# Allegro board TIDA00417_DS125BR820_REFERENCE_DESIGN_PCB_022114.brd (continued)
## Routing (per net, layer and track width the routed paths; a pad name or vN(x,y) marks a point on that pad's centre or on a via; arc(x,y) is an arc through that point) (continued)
BOT_ING_LN3_HOST_N: length 70.5
  TOP w0.178: C35.1 135.91,67.56 135.91,71.36 arc(136.14,71.91) 136.69,72.14 arc(137.36,72.41) 137.63,73.08 137.63,73.79 arc(116.37,77.13) U3.12
BOT_ING_LN3_HOST_P: length 46.1
  TOP w0.178: C34.1 135.35,67.56 135.35,71.36 arc(135.13,71.91) 134.58,72.14 arc(133.91,72.41) 133.63,73.08 133.63,73.9 arc(120.37,77.07) U3.11
BOT_ING_LN3_N: length 109.2
  TOP w0.178: U1.13 140.56,45.87 140.56,43.76 arc(140.68,43.16) 141.02,42.65 141.98,41.69 arc(142.53,40.86) 142.73,39.89 142.73,38.23 arc(142.75,38.12) 142.81,38.02 v2(142.89,37.95)
  SIG-3 w0.203: U5.L21 53.74,44.2 arc(53.97,44.15) 54.17,44.02 54.19,44.01 54.19,44 55.56,42.63 arc(57.69,41.21) 60.21,40.71 79.41,40.71 arc(81.66,40.26) 83.58,38.98 88.62,33.93 90.87,31.68 arc(93.36,30.02) 96.3,29.44 136.73,29.44 arc(141.02,31.22) 142.8,35.51 142.8,37.73 arc(142.82,37.85) v2(142.89,37.95)
BOT_ING_LN3_P: length 109.2
  TOP w0.178: U1.12 140,45.87 140,43.76 arc(140.16,42.95) 140.62,42.26 141.59,41.29 arc(142.02,40.65) 142.17,39.89 142.17,38.23 arc(142.17,38.22) 142.17,38.21 arc(142.15,38.12) 142.1,38.05 v2(142,37.95)
  SIG-3 w0.203: U5.L22 54.79,44.9 arc(54.72,44.79) 54.69,44.65 54.69,44.59 arc(54.71,44.51) 54.75,44.45 56.06,43.14 arc(57.96,41.87) 60.21,41.42 79.41,41.42 arc(81.94,40.92) 84.08,39.48 84.44,39.13 arc(84.57,39.04) 84.72,39.01 85.23,39.01 arc(85.41,38.97) 85.57,38.87 arc(85.67,38.72) 85.71,38.53 85.71,38.19 85.71,38.19 85.71,38.02 arc(85.74,37.87) 85.82,37.74 88.59,34.98 arc(88.8,34.84) 89.05,34.79 89.06,34.79 arc(89.29,34.74) 89.5,34.6 arc(89.63,34.4) 89.68,34.16 89.68,34.11 arc(89.72,33.9) 89.84,33.73 89.87,33.7 arc(90.01,33.6) 90.18,33.57 90.37,33.57 arc(90.57,33.53) 90.74,33.41 arc(90.86,33.24) 90.9,33.03 90.9,32.81 arc(90.93,32.68) 91,32.56 91.38,32.19 arc(93.63,30.68) 96.3,30.15 96.52,30.15 arc(96.73,30.19) 96.9,30.31 96.95,30.35 arc(97.14,30.49) 97.38,30.53 arc(97.61,30.49) 97.81,30.35 97.82,30.34 arc(98.03,30.2) 98.28,30.15 98.7,30.15 arc(98.95,30.2) 99.16,30.34 arc(99.38,30.48) 99.63,30.53 99.8,30.53 arc(99.97,30.5) 100.11,30.41 100.17,30.34 arc(100.38,30.2) 100.63,30.15 131.87,30.15 arc(132.29,30.23) 132.65,30.47 arc(132.83,30.59) 133.04,30.63 arc(133.36,30.57) 133.63,30.39 arc(133.9,30.21) 134.21,30.15 arc(134.52,30.21) 134.78,30.39 arc(135.06,30.57) 135.38,30.63 135.58,30.63 arc(135.76,30.6) 135.91,30.49 136.02,30.39 arc(136.29,30.21) 136.6,30.15 136.73,30.15 arc(140.52,31.72) 142.09,35.51 142.09,37.73 arc(142.07,37.85) v2(142,37.95)
BOT_ING_LN4_HOST_N: length 22.4
  TOP w0.127: 129.63,76.01 U3.10
  TOP w0.178: C25.1 127.91,67.56 127.91,71.36 arc(128.14,71.91) 128.69,72.14 arc(129.36,72.41) 129.63,73.08 129.63,73.87 arc(124.37,77.09) U3.10
BOT_ING_LN4_HOST_P: length 9.5
  TOP w0.178: C24.1 127.35,67.56 127.35,71.36 arc(127.13,71.91) 126.58,72.14 arc(125.91,72.41) 125.63,73.08 125.63,73.98 arc(125.63,75) U3.9
BOT_ING_LN4_N: length 100.9
  TOP w0.178: U1.2 135.06,45.87 135.06,45.4 arc(134.46,43.96) 133.02,43.37 132,43.37 arc(131.8,43.32) v1(131.64,43.2)
  BOTTOM w0.178: U5.L24 53.93,46.6 arc(53.98,46.6) 54.03,46.59 arc(54.15,46.54) 54.25,46.47 54.46,46.26 arc(54.99,45.9) 55.61,45.77 arc(55.62,45.77) 55.62,45.77 arc(55.99,45.57) 56.13,45.18 56.13,43.97 arc(56.24,43.43) 56.54,42.97 56.81,42.7 arc(57.47,42.26) 58.25,42.11 65.2,42.11 arc(66.54,42.37) 67.67,43.13 arc(68.26,43.52) 68.96,43.66 81.06,43.66 arc(82.81,43.31) 84.3,42.32 86.62,40 arc(88.1,37.78) 88.62,35.16 88.62,34.37 arc(88.81,33.4) 89.36,32.59 89.93,32.01 90.83,31.11 91.96,29.98 arc(94.41,28.34) 97.3,27.77 110.19,27.77 arc(113.92,28.51) 117.08,30.62 126.96,40.51 129.14,42.68 arc(129.89,43.19) 130.79,43.37 131.27,43.37 arc(131.47,43.32) v1(131.64,43.2)
BOT_ING_LN4_P: length 100
  TOP w0.178: U1.1 134.53,45.9 134.5,45.87 134.5,45.4 arc(134.07,44.36) 133.02,43.92 132,43.92 arc(131.99,43.92) 131.97,43.92 arc(131.82,43.95) 131.69,44.04 v1(131.64,44.09)
  BOTTOM w0.178: U5.L25 54.65,47.15 arc(54.59,47.01) 54.65,46.86 54.86,46.65 arc(55.21,46.41) 55.62,46.33 arc(55.64,46.33) 55.65,46.33 arc(55.67,46.32) 55.7,46.32 arc(56.41,45.94) 56.69,45.18 56.69,43.97 arc(56.76,43.64) 56.94,43.37 57.21,43.1 arc(57.69,42.78) 58.25,42.67 65.2,42.67 arc(66.32,42.89) 67.27,43.53 arc(68.05,44.04) 68.96,44.22 81.06,44.22 arc(83.02,43.83) 84.69,42.72 87.01,40.4 arc(88.62,38) 89.18,35.16 89.18,34.37 arc(89.33,33.62) 89.75,32.98 90.09,32.64 arc(90.25,32.54) 90.42,32.5 90.53,32.5 arc(90.56,32.5) 90.59,32.49 90.68,32.46 arc(90.78,32.4) 90.88,32.32 90.9,32.3 arc(91.04,32.09) 91.09,31.84 arc(91.13,31.66) 91.23,31.51 92.36,30.38 arc(94.63,28.86) 97.3,28.33 105.95,28.33 arc(106.19,28.38) 106.4,28.52 106.44,28.55 arc(106.58,28.65) 106.75,28.68 106.77,28.68 arc(106.92,28.65) 107.04,28.57 107.16,28.46 arc(107.3,28.36) 107.47,28.33 107.53,28.33 arc(107.75,28.37) 107.94,28.5 108.01,28.57 arc(108.1,28.63) 108.19,28.65 108.37,28.65 arc(108.54,28.62) 108.69,28.52 arc(108.9,28.38) 109.14,28.33 110.19,28.33 arc(113.7,29.03) 116.68,31.02 128.74,43.08 arc(129.68,43.7) 130.79,43.92 131.27,43.92 arc(131.47,43.97) v1(131.64,44.09)
BOT_INTL: length 33.8
  TOP w0.203: R81.1 J4.14
  SIG-1 w0.201: J4.14 42.87,29.65 44.76,29.65 45.41,30.29 45.41,34.33 47.38,36.31 50.57,36.31 56.05,41.79 56.05,48.12 54.9,49.27 U5.L28
BOT_LPMODE: length 40.9
  SIG-1 w0.201: J4.18 38.84,28.59 46.95,28.59 47.83,29.47 47.83,34.49 48.64,35.31 50.88,35.31 56.44,40.86 56.44,48.64 56.16,48.91 56.16,50.93 U5.L31
BOT_MODPRSL: length 40.8
  TOP w0.203: R82.1 J4.12
  SIG-1 w0.201: J4.12 44.11,31.05 42.88,32.28 42.88,35.89 44.48,37.5 49.46,37.5 52.18,40.22 52.18,47.69 U5.L27
  BOTTOM w0.203: J4.12 42.12,28.96 35.65,28.96 33.95,30.66 J4.20
BOT_MODSELL: length 30.9
  BOTTOM w0.203: U5.L8 42.9,52.2 40.28,49.59 40.28,32.25 39.03,31 J4.16
QSFP_RESETL: length 29.2
  TOP w0.203: U5.L9 51.75,51.4 52.52,52.17 53.82,52.17 54.59,51.4 U5.U9
  SIG-1 w0.201: SW20.1 43.95,69.51 47.12,66.34 47.12,53.77 U5.L9
QSFP_SCL: length 49.1
  TOP w0.203: SW19.3 v1(32.63,68.34) ; U5.L11 51.91,49.8 52.18,50.06 53.38,50.06 54.28,49.17 55.61,49.17 56.24,49.8 U5.U11
  SIG-1 w0.201: v1(32.63,68.34) 33.24,67.73 37.6,67.73 40.79,70.92 45.06,70.92 52.16,63.83 52.16,51.06 U5.L11
QSFP_SDA: length 51.1
  TOP w0.203: SW19.4 v1(35.17,68.39)
  SIG-1 w0.201: v1(35.17,68.39) 36.84,68.39 40.47,72.02 47.13,72.02 56.22,62.93 56.22,51.97 56.95,51.24 56.95,49.54 U5.U12
  BOTTOM w0.203: U5.U12 54.39,49 53.65,49.74 52.72,49.74 51.98,49 U5.L12
QSFP_VCC_3P3V: length 3.6
  TOP w0.508: R84.2 v1(46.65,25.82) ; R82.2 v1(44.11,25.82) ; R83.2 v1(54.27,25.82) ; R81.2 v1(41.57,25.82)
  vias: v1(24.95,73.7) v1(25.03,71.22) v1(25.98,73.13) v1(26.02,72.37) v1(26,70.77) v1(25.99,70.09)
RT1_DEMA0_SDA: length 120.4
  TOP w0.203: v1(131.28,49.29) 131.28,49.3 131.64,49.66 132.59,49.66 133.19,49.05 U1.49
  TOP w0.508: v1(192.82,2.58) 192.82,2.57 190.55,2.57 SW13.1
  SIG-1 w0.201: v1(192.82,2.58) 201.61,11.37 201.61,23.59 v1(200.04,25.16)
  SIG-3 w0.201: v1(131.28,49.29) 131.64,49.64 132.79,49.64 134.35,48.08 134.35,44.32 135.03,43.64 181.55,43.64 v1(200.04,25.16)
  BOTTOM w0.508: SW11.10 SW11.11 SW11.12 v1(200.04,25.16)
RT1_DEMA1_SCL: length 112.4
  TOP w0.203: U1.50 132.59,48.55 132.44,48.4 v1(131.33,48.4) ; SW13.2 196.25,5.12 199.86,8.73 v1(199.86,16.52)
  SIG-3 w0.201: v1(131.33,48.4) 131.81,47.92 131.81,47.61 132.35,47.08 133.01,47.08 133.97,46.11 133.97,43.81 134.73,43.05 173.34,43.05 v1(199.86,16.52)
  BOTTOM w0.508: SW11.7 SW11.8 SW11.9 200.4,17.54 199.86,17 v1(199.86,16.52)
RT1_DEMB0_AD1: length 98.6
  TOP w0.203: v1(130.35,48.26) 130.35,47.4 130.89,46.86 132.03,46.86 132.05,46.89 133.22,46.89 133.39,47.05 U1.53
  TOP w0.508: v1(200.04,53.1) SW12.10 SW12.11 SW12.12
  SIG-1 w0.201: v1(130.35,48.26) 130.04,48.58 130.04,57.95 132.88,60.79 196.02,60.79 200.67,56.15 200.67,53.73 v1(200.04,53.1)
RT1_DEMB1_AD0: length 96.8
  TOP w0.203: v1(130.11,46.7) 130.96,45.85 132.79,45.85 133.49,46.55 133.88,46.55 U1.54
  TOP w0.508: SW12.9 SW12.8 SW12.7 v1(200.04,60.72)
  SIG-1 w0.201: v1(200.04,60.72) 198.5,62.26 132.84,62.26 129.04,58.46 129.04,47.76 v1(130.11,46.7)
RT1_ENSMB: length 83.1
  TOP w0.203: U1.48 133.43,49.55 132.77,50.22 v1(131.7,50.22)
  SIG-1 w0.201: v1(199.66,55.64) 198.23,57.06 142.83,57.06 140.67,54.9 133.87,54.9 131.19,52.22 131.19,50.72 v1(131.7,50.22)
  BOTTOM w0.508: SW18.12 SW18.11 SW18.10 v1(199.66,55.64)
RT1_EQA0: length 67.3
  TOP w0.203: U1.20 145.11,47.05 v1(145.43,46.73)
  SIG-1 w0.201: v1(145.43,46.73) 145.43,46.73 145.38,46.78 146.3,45.86 191.66,45.86 v1(199.66,37.86)
  BOTTOM w0.508: v1(199.66,37.86) SW14.10 SW14.11 SW14.12
RT1_EQA1: length 70.1
  TOP w0.203: U1.19 v1(144.49,46.55)
  SIG-1 w0.201: v1(144.49,46.55) 144.49,46.55 147.21,43.83 186.07,43.83 v1(199.66,30.24)
  BOTTOM w0.508: SW14.9 SW14.8 SW14.7 v1(199.66,30.24)
RT1_EQB0_AD3: length 85.2
  TOP w0.203: U1.46 133.7,50.55 132.99,51.26 132.74,51.26 v1(132.72,51.28)
  TOP w0.508: SW10.12 SW10.11 SW10.10 v1(200.04,35.32)
  BOTTOM w0.203: v1(200.04,35.32) 183.67,51.68 146.63,51.68 145,50.05 144.29,50.05 141.25,53.09 134.52,53.09 v1(132.72,51.28)
RT1_EQB1_AD2: length 90
  TOP w0.203: U1.47 133.57,50.05 132.89,50.72 132.26,50.72 131.97,51.02 v1(131.97,51.04)
  TOP w0.508: SW10.9 SW10.8 SW10.7 200.02,42.94 197.98,44.98 v1(197.98,53.55)
  SIG-1 w0.201: v1(197.98,53.55) 195.89,55.64 142.54,55.64 140.59,53.68 133.95,53.68 131.97,51.7 v1(131.97,51.04)
RT1_INPUT_EN: length 34.3
  TOP w0.203: U1.22 v1(145.38,48.05)
  TOP w0.508: v1(174.89,49.03) R79.1 R80.2
  SIG-1 w0.201: v1(174.89,49.03) 146.37,49.03 145.38,48.05 v1(145.38,48.05)
RT1_MODE: length 63.7
  TOP w0.203: U1.21 v1(144.49,47.55)
  SIG-1 w0.201: v1(144.49,47.55) 144.49,47.55 144.62,47.42 195.97,47.42 v1(196.56,48)
  BOTTOM w0.508: SW18.9 SW18.8 SW18.7 196.57,48.02 v1(196.56,48)
RT1_PWDN: length 75.2
  TOP w0.203: U1.52 133.88,47.55 133.35,47.55 133.15,47.35 131.38,47.35 131.33,47.4 v1(131.33,47.41) ; R74.2 178.43,66.31 SW17.3
  TOP w0.381: R74.2 v1(177.37,66.42)
  SIG-1 w0.201: v1(177.37,66.42) 177.37,66.41 176.78,65.82 134.89,65.82 127.98,58.92 127.98,47.99 129.92,46.05 130.89,46.05 131.33,46.49 v1(131.33,47.41)
RT1_SD_TH_READ_EN: length 57.9
  TOP w0.203: SW17.4 175.68,63.77 174.26,62.34 SW16.1 174.3,58.94 SW15.4 SW15.5 SW15.6 ; U1.26 144.5,50.05 144.75,50.31 144.75,50.57 v1(144.76,50.57)
  BOTTOM w0.203: v1(144.76,50.57) 144.74,50.59 144.74,51.6 152.04,58.9 SW16.1
RT2_ALL_DONE: length 235.8
  TOP w0.203: v1(75.16,47.71) 75.16,41.6 90.6,26.16 157.35,26.16 173.33,42.14 187.9,42.14 195.73,49.97 195.73,62.39 194.35,63.77 v1(192.65,63.77)
  TOP w0.508: D1.1 v1(201.69,4.97) ; SW17.1 v1(192.65,63.77)
  SIG-3 w0.201: v1(201.69,4.97) 206.04,9.32 206.04,59.47 201.74,63.77 v1(192.65,63.77)
  BOTTOM w0.203: v1(75.16,47.71) 75.57,48.12 U2.27
RT2_DEMA0_SDA: length 156.4
  SIG-1 w0.201: v1(77.53,60.44) 77.53,66.23 104.48,93.18 160.44,93.18 167.32,86.3 194.76,86.3 v1(199.66,91.2)
  BOTTOM w0.203: U2.49 77.62,58.85 77.91,59.14 77.91,60.06 v1(77.53,60.44)
  BOTTOM w0.508: SW2.1 v1(199.66,91.2) SW4.10 SW4.11 SW4.12
RT2_DEMA1_SCL: length 154.9
  SIG-1 w0.201: v1(199.66,83.58) 198.64,82.56 164.5,82.56 159.37,87.69 101.59,87.69 78.12,64.22 78.12,60.54 v1(78.24,60.41)
  BOTTOM w0.203: SW2.2 SW4.9 ; U2.50 78.12,58.84 78.4,59.12 78.4,60.26 v1(78.24,60.41)
  BOTTOM w0.508: SW4.7 v1(199.66,83.58) ; SW4.7 SW4.8 ; SW4.7 201.96,83.58 SW4.9
RT2_DEMB0_AD1: length 146.7
  SIG-1 w0.201: v1(199.66,73.42) 197.77,75.3 168.01,75.3 157.95,85.36 102.4,85.36 79.84,62.8 v1(79.84,60.08)
  BOTTOM w0.203: U2.53 79.62,58.41 79.84,58.63 80.12,58.91 80.12,59.8 v1(79.84,60.08)
  BOTTOM w0.508: SW3.12 SW3.11 SW3.10 v1(199.66,73.42)
RT2_DEMB1_AD0: length 145.2
  SIG-1 w0.201: v1(200.04,70.88) 196.88,74.04 166.5,74.04 156.48,84.06 108.8,84.06 87.54,62.8 87.54,60.87 86.53,59.86 v1(80.63,59.86)
  BOTTOM w0.203: v1(80.63,59.86) 80.63,58.84 80.12,58.32 U2.54
  BOTTOM w0.508: v1(200.04,70.88) SW3.9 SW3.8 SW3.7
RT2_ENSMB: length 141
  TOP w0.508: SW8.10 SW8.11 SW8.12 v1(199.66,65.8)
  BOTTOM w0.203: v1(199.66,65.8) 193.33,72.12 87.29,72.12 76.87,61.71 76.87,58.99 77.12,58.75 U2.48
RT2_EQA0: length 143.7
  TOP w0.508: v1(197.55,17.61) 197.63,17.54 SW5.10 SW5.11 SW5.12
  SIG-1 w0.201: v1(197.55,17.61) 197.5,17.56 192.63,17.56 183.84,26.35 95.64,26.35 80.38,41.61 v1(80.38,47.32)
  BOTTOM w0.203: v1(80.38,47.32) 80.37,47.34 80.08,47.34 79.62,47.79 U2.20
RT2_EQA1: length 141.4
  TOP w0.508: v1(198.89,20.06) 198.91,20.08 SW5.9 SW5.8 SW5.7
  SIG-1 w0.201: v1(81.07,47.7) 81.07,42.78 95.85,28 187.23,28 195.14,20.09 198.87,20.09 v1(198.89,20.06)
  BOTTOM w0.203: U2.19 80.65,48.12 v1(81.07,47.7)
RT2_EQB0_AD3: length 148.4
  TOP w0.508: v1(194.88,87.64) 195.9,88.66 SW1.10 SW1.11 SW1.12
  BOTTOM w0.203: v1(194.88,87.64) 194.22,86.98 119.37,86.98 110.25,77.86 89.14,77.86 75.25,63.97 75.25,58.94 76.12,58.07 U2.46
RT2_EQB1_AD2: length 156.6
  TOP w0.508: SW1.8 SW1.7 SW1.8 ; SW1.8 SW1.9 ; SW1.8 v1(200.04,93.74)
  BOTTOM w0.203: v1(200.04,93.74) 196.56,93.74 195.57,92.75 195.57,84.85 194.55,83.83 120.74,83.83 111.47,74.56 87.49,74.56 75.7,62.78 75.7,59.14 76.62,58.23 U2.47
RT2_INPUT_EN: length 113
  TOP w0.508: v1(175.94,25.41) R41.1 R43.2
  SIG-1 w0.201: v1(78.59,47.3) 78.59,41.88 95.06,25.41 v1(175.94,25.41)
  BOTTOM w0.203: v1(78.59,47.3) 78.62,47.32 78.62,48.11 U2.22
RT2_MODE: length 192.6
  TOP w0.203: SW8.9 200.82,73.42 199.87,72.47 198.13,72.47 196.93,71.27 196.93,49.57 186.83,39.47 174.45,39.47 158.22,23.24 91.86,23.24 74.13,40.97 74.13,47.87 74.66,48.39 78.26,48.39 v1(79.39,47.26)
  TOP w0.508: SW8.7 SW8.9 SW8.8 SW8.7
  BOTTOM w0.203: U2.21 79.12,48.12 79.12,47.54 v1(79.39,47.26)
RT2_PWDN: length 128.8
  SIG-1 w0.201: v1(185.68,79.66) 165.48,79.66 161.23,83.91 161.25,83.91 158.51,86.65 102.1,86.65 79.12,63.67 79.12,60.15 v1(79.13,60.13)
  BOTTOM w0.203: U2.52 79.14,57.94 79.14,58.88 78.83,59.19 78.83,59.8 79.14,60.12 79.14,60.13 v1(79.13,60.13)
  BOTTOM w0.508: R42.2 185.64,78.68 185.68,78.72 v1(185.68,79.66)
  BOTTOM w0.635: R42.2 186.49,78.64 186.6,78.75 SW9.3
RT2_SD_TH: length 129
  TOP w0.203: SW6.6 SW6.5 SW6.4 175.82,16.27 SW7.1
  SIG-1 w0.201: SW7.1 173.69,18.32 99.31,18.32 75.75,41.88 v1(75.75,47.34)
  BOTTOM w0.203: v1(75.75,47.34) 75.77,47.32 76.14,47.32 76.62,47.79 U2.26
SCL: length 302.7
  TOP w0.203: SW19.2 v1(32.63,80.53) ; R5.1 J2.6 ; SW13.3 v1(180.12,5.12)
  SIG-3 w0.201: v1(32.63,80.53) 33.33,79.83 37.27,79.83 45.5,88.07 168.39,88.07 170.08,86.37 181.8,86.37 184.08,88.66 v1(187.08,88.66) 187.64,88.1 187.64,55.94 202.88,40.71 202.88,14.1 196.79,8.01 183.02,8.01 v1(180.12,5.12)
  BOTTOM w0.203: v1(180.12,5.12) 171.06,5.12 165.85,10.33 J2.6 164.38,10.33 162.17,8.12 J1.3 ; SW2.3 v1(187.08,88.66)
SDA: length 302.6
  TOP w0.203: SW13.4 v1(180.25,2.58) ; R6.1 J2.5 ; SW19.1 v1(35.17,80.53)
  SIG-3 w0.201: v1(180.25,2.58) 183.62,5.94 198.14,5.94 203.91,11.71 203.91,43.93 189.6,58.24 189.6,88.68 v1(187.08,91.2) 186.06,92.22 48.09,92.22 36.41,80.53 v1(35.17,80.53)
  BOTTOM w0.203: 164.71,7.63 J1.4 ; 164.71,7.63 165.87,7.63 170.93,2.58 v1(180.25,2.58) ; 164.71,7.63 164.71,7.66 J2.5 ; SW2.4 v1(187.08,91.2)
TOP_EGR_LN1_HOST_N: length 11.2
  BOTTOM w0.178: 98.3,67.03 97.57,67.03 arc(96.9,66.76) 96.62,66.09 arc(96.4,65.54) 95.85,65.31 92.04,65.31 C7.1 ; 98.3,67.03 99.96,67.03 ; 98.3,67.03 arc(99.4,67.03) U4.16
TOP_EGR_LN1_HOST_P: length 9.5
  BOTTOM w0.178: C8.1 92.04,64.75 95.85,64.75 arc(96.4,64.52) 96.62,63.97 arc(96.9,63.31) 97.57,63.03 99.99,63.03 arc(100.24,63.03) U4.15
TOP_EGR_LN1_N: length 24.7
  BOTTOM w0.178: U5.U5 58.65,54.35 arc(58.59,54.21) 58.65,54.06 58.81,53.9 arc(58.92,53.83) 59.05,53.8 59.29,53.8 arc(59.67,53.96) 59.83,54.35 59.83,57.63 arc(59.93,58.14) 60.22,58.57 arc(60.66,58.86) 61.17,58.96 63.48,58.96 arc(64.42,58.78) 65.22,58.24 65.51,57.95 arc(65.64,57.87) 65.79,57.84 66.05,57.84 arc(66.19,57.81) 66.31,57.73 66.34,57.7 arc(66.44,57.55) 66.48,57.38 66.48,57.11 arc(66.5,57) 66.56,56.9 66.68,56.79 arc(66.78,56.72) 66.91,56.69 67.14,56.69 arc(67.32,56.65) 67.48,56.55 67.52,56.51 arc(67.6,56.39) 67.62,56.26 67.62,56 arc(67.65,55.85) 67.74,55.73 69.13,54.33 arc(70.15,53.65) 71.36,53.41 72.8,53.41 arc(72.88,53.43) 72.95,53.47 arc(73.31,53.71) 73.73,53.8 75.44,53.8 75.47,53.77 U2.38
TOP_EGR_LN1_P: length 24.7
  BOTTOM w0.178: U5.U6 57.93,53.8 arc(58.03,53.79) 58.13,53.76 arc(58.19,53.72) 58.25,53.67 58.41,53.51 arc(58.7,53.31) 59.05,53.24 59.29,53.24 arc(60.07,53.57) 60.39,54.35 60.39,57.63 arc(60.45,57.93) 60.62,58.18 arc(60.87,58.35) 61.17,58.41 63.48,58.41 arc(64.21,58.26) 64.83,57.84 68.74,53.93 arc(69.94,53.13) 71.36,52.85 72.8,52.85 arc(73.09,52.91) 73.34,53.08 arc(73.52,53.19) 73.73,53.24 75.44,53.24 75.47,53.26 U2.37
TOP_EGR_LN2_HOST_N: length 9.5
  BOTTOM w0.178: U4.12 97.57,51.03 arc(96.9,50.76) 96.62,50.09 arc(96.4,49.54) 95.85,49.31 92.04,49.31 C11.1
TOP_EGR_LN2_HOST_P: length 9.5
  BOTTOM w0.178: C12.1 92.04,48.75 95.85,48.75 arc(96.4,48.52) 96.62,47.97 arc(96.9,47.31) 97.57,47.03 U4.11
TOP_EGR_LN2_N: length 15.1
  BOTTOM w0.178: U5.U34 62.64,54.35 arc(62.59,54.21) 62.64,54.06 62.76,53.95 arc(62.86,53.88) 62.97,53.86 63.08,53.86 arc(63.17,53.84) 63.24,53.8 arc(63.3,53.71) 63.32,53.61 63.32,53.49 arc(63.34,53.4) 63.39,53.32 63.39,53.32 arc(63.5,53.25) 63.62,53.22 63.7,53.22 arc(63.8,53.2) 63.87,53.15 arc(63.94,53.06) 63.96,52.95 63.96,52.9 arc(63.99,52.76) 64.06,52.64 64.15,52.55 arc(64.44,52.37) 64.77,52.3 66.25,52.3 arc(66.62,52.23) 66.93,52.02 67.42,51.53 arc(67.68,51.36) 67.98,51.3 68.08,51.3 arc(68.17,51.31) 68.25,51.37 68.47,51.58 arc(68.58,51.66) 68.72,51.69 68.86,51.69 arc(69,51.66) 69.13,51.57 69.27,51.43 arc(69.42,51.33) 69.6,51.3 75.44,51.3 75.47,51.27 U2.33
TOP_EGR_LN2_P: length 15.1
  BOTTOM w0.178: U2.32 75.44,50.74 67.98,50.74 arc(67.46,50.84) 67.02,51.14 66.53,51.62 arc(66.4,51.71) 66.25,51.74 64.77,51.74 arc(64.22,51.85) 63.76,52.16 62.56,53.36 62.56,53.36 62.24,53.67 arc(62.1,53.77) 61.93,53.8 U5.U33
TOP_EGR_LN3_HOST_N: length 9.5
  BOTTOM w0.178: U4.14 99.96,59.03 97.57,59.03 arc(96.9,58.76) 96.62,58.09 arc(96.4,57.54) 95.85,57.31 92.04,57.31 C9.1
TOP_EGR_LN3_HOST_P: length 9.5
  BOTTOM w0.178: C10.1 92.04,56.75 95.85,56.75 arc(96.4,56.52) 96.62,55.97 arc(96.9,55.31) 97.57,55.03 99.99,55.03 U4.13
TOP_EGR_LN3_N: length 16.3
  BOTTOM w0.178: U5.U37 62.65,56.75 arc(62.59,56.61) 62.65,56.46 62.85,56.26 arc(62.97,56.18) 63.11,56.15 63.56,56.15 arc(64.35,55.82) 64.68,55.03 64.68,54.22 arc(64.71,54.06) 64.8,53.93 arc(64.93,53.84) 65.08,53.81 65.18,53.81 arc(65.28,53.83) 65.37,53.89 65.54,54.07 arc(65.64,54.13) 65.74,54.15 arc(65.85,54.13) 65.94,54.07 66.12,53.89 arc(66.2,53.83) 66.3,53.81 66.3,53.81 arc(66.41,53.84) 66.5,53.89 66.61,54.01 arc(66.72,54.08) 66.85,54.11 66.93,54.11 arc(67.06,54.08) 67.17,54.01 67.27,53.9 arc(67.37,53.84) 67.49,53.81 67.5,53.81 arc(68,53.71) 68.43,53.43 69.02,52.84 arc(69.72,52.44) 70.52,52.3 73.33,52.3 arc(73.52,52.33) 73.67,52.44 arc(73.75,52.49) 73.85,52.51 74.03,52.51 arc(74.1,52.5) 74.16,52.46 74.23,52.38 arc(74.33,52.32) 74.43,52.3 75.44,52.3 75.47,52.27 U2.35
TOP_EGR_LN3_P: length 16.3
  BOTTOM w0.178: U2.34 75.47,51.76 75.44,51.74 70.52,51.74 arc(69.52,51.91) 68.64,52.42 68.03,53.03 arc(67.78,53.2) 67.5,53.26 65.08,53.26 arc(64.72,53.33) 64.4,53.54 arc(64.19,53.85) 64.12,54.22 64.12,55.03 arc(63.96,55.43) 63.56,55.59 63.11,55.59 arc(62.76,55.66) 62.45,55.87 62.25,56.07 arc(62.16,56.14) 62.05,56.18 arc(61.99,56.2) 61.93,56.2 U5.U36
TOP_EGR_LN4_HOST_N: length 9
  BOTTOM w0.178: 99.96,43.03 97.57,43.03 arc(96.9,42.76) 96.62,42.09 arc(96.4,41.54) 95.85,41.31 92.04,41.31 C13.1
TOP_EGR_LN4_HOST_P: length 11
  BOTTOM w0.178: 99.99,39.03 98.53,39.03 ; 98.53,39.03 97.57,39.03 arc(96.9,39.31) 96.62,39.97 arc(96.4,40.52) 95.85,40.75 92.04,40.75 C14.1 ; 98.53,39.03 arc(99.51,39.03) U4.9
TOP_EGR_LN4_N: length 27.7
  SIG-2 w0.203: U5.U2 58.79,56.9 arc(58.72,56.79) 58.69,56.65 58.69,56.59 arc(58.71,56.51) 58.75,56.45 58.9,56.3 arc(58.96,56.26) 59.04,56.24 59.31,56.24 arc(59.69,56.4) 59.84,56.78 59.84,57.38 arc(60.39,58.7) 61.7,59.25 64.77,59.25 arc(65.73,59.05) 66.54,58.51 66.56,58.49 arc(66.7,58.4) 66.87,58.36 66.95,58.36 arc(67.09,58.33) 67.21,58.25 67.32,58.15 arc(67.41,58.01) 67.44,57.86 67.44,57.72 arc(67.46,57.62) 67.51,57.54 arc(67.98,56.84) 68.14,56.02 68.14,55.68 arc(68.18,55.45) 68.31,55.26 68.49,55.08 arc(68.59,54.86) 68.49,54.64 68.3,54.44 arc(68.14,54.06) 68.3,53.68 68.45,53.53 arc(68.56,53.26) 68.45,52.99 68.3,52.84 arc(68.18,52.67) 68.14,52.46 68.14,52.24 arc(69.02,50.11) 71.15,49.23 71.48,49.23 arc(71.6,49.25) v2(71.7,49.32)
  BOTTOM w0.178: U2.31 75.47,50.27 75.44,50.3 74.93,50.3 arc(74.16,50.14) 73.51,49.71 73.44,49.63 arc(72.91,49.28) 72.28,49.16 72.09,49.16 arc(71.88,49.2) v2(71.7,49.32)
TOP_EGR_LN4_P: length 27.7
  SIG-2 w0.203: v2(71.7,48.43) arc(71.6,48.5) 71.48,48.52 71.15,48.52 arc(68.52,49.61) 67.43,52.24 67.43,56.02 arc(67.32,56.57) 67.01,57.04 66.52,57.52 66.08,57.96 arc(66.07,57.98) 66.05,58 arc(65.43,58.39) 64.7,58.53 61.7,58.53 arc(60.89,58.2) 60.55,57.38 60.55,56.78 arc(60.19,55.9) 59.31,55.53 59.04,55.53 arc(58.69,55.6) 58.39,55.8 58.35,55.85 arc(57.96,56.11) U5.U3
  BOTTOM w0.178: U2.30 75.47,49.76 75.44,49.74 74.93,49.74 arc(74.38,49.63) 73.9,49.31 73.83,49.24 arc(73.12,48.76) 72.28,48.6 72.09,48.6 arc(71.88,48.55) v2(71.7,48.43)
TOP_ING_LN1_HOST_N: length 9.5
  BOTTOM w0.178: U4.5 107.44,51.03 arc(108.1,50.76) 108.38,50.09 arc(108.61,49.54) 109.16,49.31 112.96,49.31 C29.1
TOP_ING_LN1_HOST_P: length 9.5
  BOTTOM w0.178: U4.6 107.44,47.03 arc(108.1,47.31) 108.38,47.97 arc(108.61,48.52) 109.16,48.75 112.96,48.75 C28.1
TOP_ING_LN1_N: length 91
  TOP w0.178: U1.6 137.06,45.87 137.06,43.88 arc(136.88,42.97) 136.36,42.2 136,41.84 arc(135.6,41.25) 135.47,40.55 135.47,40.26 arc(135.49,40.14) 135.56,40.04 v1(135.63,39.97)
  SIG-2 w0.203: U5.U21 61.74,44.2 arc(61.97,44.15) 62.17,44.02 62.19,44.01 62.19,44 62.39,43.8 arc(62.83,43.51) 63.35,43.41 68.76,43.41 arc(70.25,43.7) 71.52,44.55 arc(72.62,45.28) 73.91,45.54 82.32,45.54 arc(85.29,44.95) 87.8,43.27 94.12,36.95 96.86,34.21 arc(99.27,32.6) 102.12,32.03 127.04,32.03 arc(130.79,32.78) 133.97,34.9 134.16,35.09 arc(135.18,36.62) 135.54,38.43 135.54,39.75 arc(135.57,39.87) v1(135.63,39.97)
TOP_ING_LN1_P: length 91
  TOP w0.178: U1.5 136.5,45.87 136.5,43.88 arc(136.36,43.19) 135.96,42.59 135.6,42.23 arc(135.09,41.46) 134.91,40.55 134.91,40.37 arc(134.86,40.15) v1(134.74,39.97)
  SIG-2 w0.203: U5.U22 62.79,44.9 arc(62.72,44.79) 62.69,44.65 62.69,44.59 arc(62.71,44.51) 62.75,44.45 62.9,44.3 arc(63.1,44.17) 63.35,44.12 68.76,44.12 arc(69.98,44.36) 71.02,45.05 arc(72.34,45.94) 73.91,46.25 82.32,46.25 arc(85.56,45.61) 88.3,43.77 88.6,43.47 arc(88.76,43.37) 88.95,43.33 89.24,43.33 arc(89.55,43.27) 89.81,43.1 89.89,43.02 arc(90,42.85) 90.04,42.65 90.04,42.44 90.04,42.24 arc(90.08,42.05) 90.18,41.9 90.35,41.72 arc(90.55,41.59) 90.77,41.55 91.17,41.55 arc(91.63,41.36) 91.82,40.9 91.82,40.66 arc(91.83,40.54) 91.85,40.42 arc(91.95,40.18) 92.11,39.97 94.62,37.46 97.36,34.72 arc(99.55,33.26) 102.12,32.74 102.35,32.74 arc(102.57,32.79) 102.75,32.91 102.85,33.01 arc(103.15,33.21) 103.49,33.27 arc(103.66,33.24) 103.81,33.14 103.92,33.03 arc(104.24,32.82) 104.61,32.74 104.85,32.74 arc(105.06,32.79) 105.25,32.91 105.35,33.01 arc(105.64,33.21) 105.99,33.27 arc(106.27,33.22) 106.5,33.06 arc(106.86,32.83) 107.27,32.74 122.52,32.74 arc(122.79,32.8) 123.01,32.95 arc(123.24,33.1) 123.51,33.16 123.71,33.16 arc(123.9,33.12) 124.05,33.02 124.12,32.95 arc(124.35,32.8) 124.62,32.74 124.82,32.74 arc(125.09,32.8) 125.32,32.95 arc(125.55,33.1) 125.82,33.16 126.01,33.16 arc(126.19,33.12) 126.35,33.02 126.42,32.95 arc(126.64,32.8) 126.91,32.74 127.04,32.74 arc(130.52,33.44) 133.47,35.41 133.65,35.59 arc(134.52,36.9) 134.83,38.43 134.83,39.75 arc(134.81,39.87) v1(134.74,39.97)
TOP_ING_LN2_HOST_N: length 107.5
  BOTTOM w0.178: C33.1 112.96,65.31 109.16,65.31 arc(108.61,65.54) 108.38,66.09 arc(108.1,66.76) 107.44,67.03 105.9,67.03 arc(106.6,34.57) U4.1
TOP_ING_LN2_HOST_P: length 79.8
  BOTTOM w0.178: C32.1 112.96,64.75 109.16,64.75 arc(108.61,64.52) 108.38,63.97 arc(108.1,63.31) 107.44,63.03 107.01,63.03 arc(108.26,38.57) U4.2
TOP_ING_LN2_N: length 102
  TOP w0.178: U1.11 139.56,45.87 139.56,42.33 arc(139.6,42.11) 139.72,41.92 139.78,41.87 arc(140.19,41.26) 140.33,40.54 140.33,40.24 arc(140.35,40.14) 140.41,40.05 v2(140.5,39.97)
  SIG-3 w0.203: U5.U15 57.74,46.6 arc(57.87,46.59) 58,46.54 arc(58.09,46.49) 58.17,46.42 58.19,46.41 58.19,46.4 58.53,46.06 arc(58.86,45.82) 59.25,45.69 arc(59.26,45.69) 59.27,45.69 arc(59.31,45.68) 59.35,45.68 arc(59.37,45.68) 59.39,45.68 arc(59.79,45.51) 59.96,45.1 59.96,43.97 arc(60.5,42.67) 61.8,42.13 74.15,42.13 arc(75.06,42.31) 75.82,42.82 arc(76.21,43.09) 76.68,43.18 79.1,43.18 arc(83.01,42.4) 86.32,40.19 94.02,32.49 arc(94.76,32) 95.63,31.82 134.82,31.82 arc(136.4,32.14) 137.75,33.04 arc(137.97,33.22) 138.17,33.41 139.57,34.8 arc(140.19,35.73) 140.41,36.83 140.41,39.75 arc(140.43,39.87) v2(140.5,39.97)
TOP_ING_LN2_P: length 102
  TOP w0.178: v2(139.61,39.97) 139.7,40.06 arc(139.75,40.14) 139.77,40.24 139.77,40.54 arc(139.67,41.04) 139.38,41.47 139.33,41.53 arc(139.08,41.89) 139,42.33 139,45.87 U1.10
  SIG-3 w0.203: U5.U14 58.79,47.3 arc(58.72,47.19) 58.69,47.05 58.69,46.99 arc(58.71,46.91) 58.75,46.85 59.04,46.56 arc(59.19,46.45) 59.37,46.39 arc(59.38,46.39) 59.39,46.39 arc(60.3,46.01) 60.68,45.1 60.68,43.97 arc(61,43.17) 61.8,42.84 62.74,42.84 arc(62.98,42.89) 63.18,43.03 63.21,43.05 arc(63.38,43.17) 63.58,43.21 63.8,43.21 arc(64.04,43.16) 64.24,43.03 arc(64.45,42.89) 64.68,42.84 71.52,42.84 arc(71.77,42.89) 71.98,43.04 arc(72.19,43.18) 72.44,43.23 72.52,43.23 arc(72.77,43.18) 72.98,43.04 arc(73.2,42.89) 73.44,42.84 74.15,42.84 arc(74.79,42.97) 75.32,43.33 arc(75.94,43.74) 76.68,43.89 79.1,43.89 arc(83.28,43.06) 86.82,40.69 94.52,32.99 arc(95.03,32.65) 95.63,32.53 95.96,32.53 arc(96.28,32.6) 96.54,32.77 96.56,32.8 arc(96.85,32.99) 97.19,33.06 arc(97.45,33.01) 97.66,32.86 97.75,32.78 arc(98.02,32.6) 98.34,32.53 98.49,32.53 arc(98.64,32.56) 98.76,32.64 98.91,32.8 arc(99.2,32.99) 99.54,33.06 arc(99.77,33.01) 99.96,32.89 arc(100.35,32.63) 100.81,32.53 128.9,32.53 arc(129.24,32.6) 129.52,32.79 129.67,32.94 arc(129.83,33.05) 130.03,33.09 130.09,33.09 arc(130.34,33.04) 130.56,32.89 130.66,32.79 arc(130.94,32.6) 131.28,32.53 arc(131.54,32.59) 131.76,32.74 131.81,32.79 arc(132.1,32.98) 132.44,33.04 132.64,33.04 arc(132.84,33.01) 133,32.9 133.11,32.79 arc(133.39,32.6) 133.72,32.53 134.77,32.53 arc(136.13,32.8) 137.28,33.57 arc(137.48,33.73) 137.67,33.91 137.79,34.03 arc(137.88,34.17) 137.91,34.33 137.91,34.53 arc(137.94,34.68) 138.03,34.81 arc(138.16,34.9) 138.31,34.93 138.42,34.93 arc(138.67,34.98) 138.88,35.12 139.07,35.31 arc(139.53,36) 139.69,36.83 139.69,39.75 arc(139.67,39.87) v2(139.61,39.97)
TOP_ING_LN3_HOST_N: length 9.5
  BOTTOM w0.178: U4.7 107.44,43.03 arc(108.1,42.76) 108.38,42.09 arc(108.61,41.54) 109.16,41.31 112.96,41.31 C27.1
TOP_ING_LN3_HOST_P: length 9.5
  BOTTOM w0.178: C26.1 112.96,40.75 109.16,40.75 arc(108.61,40.52) 108.38,39.97 arc(108.1,39.31) 107.44,39.03 U4.8
TOP_ING_LN3_N: length 85
  TOP w0.178: U1.4 136.06,45.87 136.06,44.49 arc(135.93,43.84) 135.56,43.29 133.57,41.3 arc(132.81,40.8) 131.93,40.62 130.32,40.62 arc(130.25,40.61) 130.18,40.56 v2(130.07,40.45)
  SIG-3 w0.203: U5.U24 61.74,46.6 arc(61.85,46.59) 61.96,46.56 arc(62.07,46.5) 62.17,46.42 62.19,46.41 62.19,46.4 62.39,46.2 arc(62.4,46.2) 62.4,46.19 62.56,46.04 arc(62.92,45.8) 63.35,45.71 arc(63.46,45.69) 63.56,45.62 64.77,44.41 arc(65.5,43.93) 66.35,43.76 69.92,43.76 arc(71.01,43.97) 71.93,44.59 arc(72.59,45.03) 73.37,45.19 81.4,45.19 arc(84.78,44.51) 87.64,42.6 93.91,36.33 arc(96.27,34.76) 99.05,34.2 114.87,34.2 arc(118.18,34.86) 120.99,36.74 121.74,37.49 arc(125.12,39.75) 129.11,40.54 129.99,40.54 arc(130.05,40.52) v2(130.07,40.45)
TOP_ING_LN3_P: length 84.1
  TOP w0.178: U1.3 135.5,45.87 135.5,44.49 arc(135.41,44.06) 135.17,43.69 134.42,42.94 133.17,41.69 arc(132.6,41.31) 131.93,41.18 130.32,41.18 arc(130.25,41.19) 130.18,41.23 v2(130.07,41.34)
  SIG-3 w0.203: U5.U25 62.79,47.3 arc(62.72,47.19) 62.69,47.05 62.69,46.99 arc(62.71,46.91) 62.75,46.85 62.9,46.7 arc(62.9,46.7) 62.9,46.7 63.06,46.54 arc(63.19,46.45) 63.35,46.42 arc(63.73,46.34) 64.06,46.12 65.25,44.94 65.27,44.91 arc(65.77,44.58) 66.35,44.47 66.65,44.47 arc(66.79,44.49) 66.9,44.57 67.07,44.74 arc(67.23,44.84) 67.41,44.88 67.61,44.88 arc(67.88,44.83) 68.11,44.67 68.21,44.57 arc(68.33,44.49) 68.46,44.47 69.92,44.47 arc(70.74,44.63) 71.43,45.09 arc(72.32,45.69) 73.37,45.9 81.4,45.9 arc(85.05,45.17) 88.15,43.1 94.41,36.84 arc(96.54,35.42) 99.05,34.92 109.78,34.92 arc(109.92,34.94) 110.03,35.02 110.14,35.12 arc(110.36,35.28) 110.63,35.33 110.83,35.33 arc(111.02,35.29) 111.17,35.19 111.24,35.12 111.34,35.02 arc(111.46,34.94) 111.59,34.92 111.99,34.92 arc(112.13,34.94) 112.24,35.02 112.34,35.12 arc(112.57,35.28) 112.84,35.33 113.04,35.33 arc(113.23,35.29) 113.38,35.19 113.45,35.12 113.55,35.02 arc(113.67,34.94) 113.8,34.92 114.87,34.92 arc(117.91,35.52) 120.49,37.25 121.24,37.99 arc(124.85,40.41) 129.11,41.25 129.99,41.25 arc(130.05,41.28) v2(130.07,41.34)
TOP_ING_LN4_HOST_N: length 55.3
  BOTTOM w0.178: C31.1 112.96,57.31 109.16,57.31 arc(108.61,57.54) 108.38,58.09 arc(108.1,58.76) 107.44,59.03 106.93,59.03 arc(108.15,42.57) U4.3
TOP_ING_LN4_HOST_P: length 31
  BOTTOM w0.178: C30.1 112.96,56.75 109.16,56.75 arc(108.61,56.52) 108.38,55.97 arc(108.1,55.31) 107.44,55.03 107.11,55.03 arc(108.42,46.57) U4.4
TOP_ING_LN4_N: length 99.5
  TOP w0.178: U1.8 138.06,45.87 138.06,38.31 arc(138.06,38.3) 138.06,38.28 arc(138.06,38.26) 138.06,38.23 arc(138.08,38.12) 138.15,38.02 v1(138.22,37.95)
  SIG-2 w0.203: U5.U18 57.74,44.2 arc(57.97,44.15) 58.17,44.02 58.19,44.01 58.19,44 59.25,42.95 arc(60.25,42.28) 61.42,42.05 70.3,42.05 arc(71.45,42.27) 72.42,42.92 arc(72.71,43.12) 73.06,43.19 79.18,43.19 arc(83.05,42.42) 86.32,40.23 94.64,31.91 arc(98.01,29.66) 101.99,28.87 127.06,28.87 arc(131.32,29.72) 134.94,32.13 137.41,34.61 arc(137.95,35.4) 138.13,36.34 138.13,37.73 arc(138.16,37.85) v1(138.22,37.95)
TOP_ING_LN4_P: length 99.5
  TOP w0.178: U1.7 137.5,45.87 137.5,38.31 arc(137.5,38.28) 137.5,38.25 arc(137.48,38.13) 137.42,38.03 v1(137.33,37.95)
  SIG-2 w0.203: U5.U17 58.79,44.9 arc(58.72,44.79) 58.69,44.65 58.69,44.59 arc(58.71,44.51) 58.75,44.45 59.75,43.45 arc(60.52,42.94) 61.42,42.76 70.3,42.76 arc(71.18,42.93) 71.92,43.43 arc(72.44,43.77) 73.06,43.9 79.18,43.9 arc(83.32,43.07) 86.83,40.73 86.9,40.66 arc(87.17,40.48) 87.49,40.41 87.54,40.41 arc(87.81,40.36) 88.03,40.21 arc(88.18,39.98) 88.24,39.71 88.24,39.46 arc(88.26,39.33) 88.34,39.22 88.58,38.97 arc(88.74,38.87) 88.93,38.83 89.12,38.83 arc(89.39,38.78) 89.62,38.63 arc(89.77,38.4) 89.82,38.13 89.82,38.08 arc(89.88,37.76) 90.06,37.49 95.14,32.42 arc(98.28,30.32) 101.99,29.58 102.23,29.58 arc(102.45,29.62) 102.64,29.75 102.72,29.82 arc(102.99,30) 103.31,30.07 arc(103.47,30.03) 103.6,29.94 103.68,29.87 arc(104,29.65) 104.38,29.58 104.53,29.58 arc(104.67,29.61) 104.78,29.68 104.92,29.82 arc(105.19,30) 105.51,30.07 arc(105.79,30.01) 106.03,29.85 arc(106.33,29.65) 106.69,29.58 122.52,29.58 arc(122.81,29.64) 123.06,29.8 123.07,29.81 arc(123.3,29.97) 123.58,30.03 123.76,30.03 arc(123.92,29.99) 124.06,29.9 124.16,29.8 arc(124.41,29.64) 124.7,29.58 124.73,29.58 arc(125.03,29.64) 125.27,29.8 arc(125.52,29.97) 125.82,30.03 126.05,30.03 arc(126.26,29.98) 126.44,29.86 126.5,29.8 arc(126.75,29.64) 127.04,29.58 127.06,29.58 arc(131.05,30.37) 134.43,32.63 134.98,33.18 arc(135.14,33.42) 135.19,33.69 arc(135.25,33.97) 135.41,34.2 arc(135.64,34.36) 135.92,34.41 arc(136.19,34.47) 136.43,34.63 136.91,35.11 arc(137.29,35.68) 137.42,36.34 137.42,37.73 arc(137.4,37.85) v1(137.33,37.95)
TOP_INTL: length 32.7
  TOP w0.203: R83.1 J4.4
  SIG-1 w0.201: U5.U28 64.48,48.21 64.48,33.35 60.3,29.17 56.05,29.17 J4.4
TOP_LPMODE: length 41.2
  SIG-1 w0.201: U5.U31 64.46,50.63 64.46,49.81 66.92,47.36 66.92,33.6 61.74,28.42 51.67,28.42 49.19,30.9 J4.8
TOP_MODPRSL: length 34.8
  TOP w0.203: R84.1 J4.10
  SIG-1 w0.201: J4.2 57.81,30.95 59.8,32.94 59.8,41.84 60.39,42.44 60.39,47.9 U5.U27
  BOTTOM w0.203: J4.2 55.5,29.65 47.82,29.65 46.65,30.81 J4.10
TOP_MODSELL: length 26.1
  SIG-1 w0.201: U5.U8 59.99,51.11 59.99,43.48 50.56,34.05 50.56,32.47 51.73,31.31 J4.6
VIH: length 28.5
  TOP w0.381: R74.1 v1(178.32,68.57) ; R63.1 v1(195.06,53.86)
  TOP w0.508: R8.1 v1(214.91,91.98) ; v1(169.91,7.79) R6.2 ; R44.1 v1(214.78,31.02) ; R57.1 v1(214.91,56.42) ; R5.2 169.85,10.33 v1(169.88,10.35) ; R71.2 v1(208.67,2.43) ; v1(179.23,25.41) R41.2 ; R52.1 v1(214.78,48.8) ; R31.1 v1(214.78,20.86) ; R35.1 v1(214.91,66.58) ; R1.1 v1(214.91,84.36) ; R34.2 v1(208.67,4.97) ; R47.1 v1(214.78,38.64) ; v1(169.88,12.89) 169.85,12.87 R2.2 ; R38.1 v1(214.91,74.2) ; R26.1 v1(196.86,11.24) ; R25.1 v1(214.78,13.24) ; v1(178.19,49.03) R79.2
  BOTTOM w0.381: R20.1 v1(215.91,71.01) ; R56.1 v1(215.71,17.54) ; R76.1 v1(215.79,53.1) ; R13.1 v1(215.91,96.28) ; R50.1 v1(215.71,25.16) ; R14.1 v1(215.91,78.5) ; R72.1 v1(215.91,60.72) ; R68.1 v1(215.66,35.32) ; R62.1 v1(215.71,42.94) ; R19.1 v1(215.91,88.66)
  BOTTOM w0.508: R42.1 185.69,76.52 v1(185.71,76.5)
N14524358: length 3
  TOP w0.203: R11.2 J2.3
N14524360: length 3
  TOP w0.203: R9.2 J2.2
N14524362: length 3
  TOP w0.203: R4.2 J2.1
N14693554: length 3
  TOP w0.203: R2.1 J2.7
N16748072: length 103.3
  TOP w0.178: C1.2 151.91,89.21 151.91,89.83 arc(151.67,91.07) 150.96,92.12 148.31,94.78 arc(144.2,97.52) 139.35,98.49 111.91,98.49 arc(104.17,96.95) 97.61,92.56 97.2,92.15 85.22,80.17 arc(82.77,76.5) 81.91,72.17 81.91,62.87 arc(81.86,62.65) v1(81.74,62.47)
  BOTTOM w0.178: U2.1 80.8,57.3 81.11,57.3 arc(81.67,57.53) 81.91,58.1 81.91,60.62 arc(81.85,60.77) 81.7,60.83 81.5,60.83 arc(81.29,61.04) 81.5,61.25 81.7,61.25 arc(81.85,61.31) 81.91,61.46 81.91,62.07 arc(81.86,62.29) v1(81.74,62.47)
N16748078: length 103.3
  TOP w0.178: C2.2 151.35,89.21 151.35,89.83 arc(151.15,90.85) 150.57,91.72 150.35,91.94 arc(150.2,92.04) 150.03,92.08 arc(149.86,92.11) 149.71,92.21 149.67,92.25 arc(149.57,92.39) 149.54,92.57 arc(149.51,92.74) 149.41,92.88 149.38,92.92 arc(149.23,93.02) 149.05,93.05 arc(148.88,93.09) 148.73,93.19 148.7,93.21 arc(148.6,93.36) 148.56,93.54 arc(148.53,93.71) 148.43,93.86 147.91,94.38 arc(143.98,97.01) 139.35,97.93 139.19,97.93 arc(138.95,97.88) 138.74,97.74 138.63,97.63 arc(138.51,97.55) 138.37,97.52 138.33,97.52 arc(138.15,97.56) 138,97.66 137.87,97.79 arc(137.72,97.89) 137.54,97.93 137.49,97.93 arc(137.35,97.9) 137.24,97.83 137.08,97.66 arc(136.92,97.56) 136.74,97.52 136.69,97.52 arc(136.55,97.55) 136.42,97.63 136.31,97.74 arc(136.11,97.88) 135.86,97.93 111.91,97.93 arc(104.39,96.43) 98.01,92.17 97.85,92.01 arc(97.75,91.86) 97.71,91.67 97.71,91.53 arc(97.68,91.4) 97.61,91.29 97.57,91.25 arc(97.41,91.14) 97.22,91.1 97.17,91.1 arc(96.79,90.94) 96.63,90.56 96.63,90.53 arc(96.6,90.33) 96.48,90.17 arc(96.32,90.06) 96.12,90.02 arc(95.88,89.97) 95.67,89.83 85.62,79.78 arc(83.29,76.29) 82.47,72.17 82.47,71.91 arc(82.53,71.6) 82.7,71.34 82.81,71.24 arc(82.94,70.92) 82.81,70.6 82.63,70.42 arc(82.51,70.24) 82.47,70.02 82.47,70.02 arc(82.51,69.8) 82.63,69.62 82.79,69.46 arc(82.94,69.11) 82.79,68.75 82.7,68.66 arc(82.53,68.4) 82.47,68.09 82.47,62.87 arc(82.51,62.65) v1(82.63,62.47)
  BOTTOM w0.178: U2.2 80.8,56.74 81.11,56.74 arc(82.07,57.13) 82.47,58.1 82.47,62.07 arc(82.51,62.29) v1(82.63,62.47)
N16748084: length 91.3
  TOP w0.178: C3.2 143.91,89.21 143.91,89.61 arc(143.72,90.6) 143.15,91.44 141,93.59 arc(138.49,95.27) 135.52,95.86 110.61,95.86 arc(106.88,95.12) 103.72,93.01 89.86,79.15 arc(85.77,73.03) 84.34,65.81 84.34,61.2 arc(84.29,60.98) v1(84.17,60.8)
  BOTTOM w0.178: v1(84.17,60.8) 84.28,60.69 arc(84.32,60.63) 84.34,60.56 84.34,60.17 arc(84.32,60.09) 84.28,60.03 arc(84.21,59.98) 84.13,59.97 83.93,59.97 arc(83.72,59.76) 83.93,59.54 84.1,59.54 arc(84.19,59.53) 84.27,59.48 arc(84.32,59.4) 84.34,59.31 84.34,58.98 arc(84.22,58.39) 83.88,57.89 82.73,56.73 arc(82.24,56.41) 81.67,56.3 80.8,56.3 U2.3
N16748090: length 91.4
  TOP w0.178: C4.2 143.35,89.21 143.35,89.61 arc(143.2,90.39) 142.76,91.04 140.61,93.2 arc(138.27,94.76) 135.52,95.3 135.05,95.3 arc(134.77,95.25) 134.54,95.09 134.48,95.04 arc(134.42,94.98) 134.35,94.95 134.29,94.92 arc(134.16,94.9) 134.03,94.92 133.94,94.96 arc(133.79,95.04) 133.65,95.15 arc(133.48,95.26) 133.28,95.3 133.25,95.3 arc(133.08,95.27) 132.94,95.18 132.81,95.05 arc(132.63,94.93) 132.41,94.88 arc(132.19,94.93) 132.01,95.05 131.97,95.09 arc(131.73,95.25) 131.46,95.3 110.61,95.3 arc(107.09,94.6) 104.12,92.61 103.99,92.49 arc(103.86,92.3) 103.82,92.07 103.82,91.9 arc(103.79,91.74) 103.69,91.6 103.5,91.4 arc(103.35,91.31) 103.19,91.27 arc(102.74,91.09) 102.55,90.64 arc(102.53,90.51) 102.45,90.4 102.26,90.21 arc(102.13,90.12) 101.98,90.09 101.81,90.09 arc(101.61,90.05) 101.43,89.93 92.78,81.28 arc(92.64,81.07) 92.59,80.83 92.59,80.74 arc(92.56,80.57) 92.47,80.43 arc(92.32,80.33) 92.15,80.3 92.04,80.3 arc(91.83,80.26) 91.66,80.14 91.64,80.12 arc(91.54,79.97) 91.5,79.8 91.5,79.6 arc(91.47,79.45) 91.39,79.32 arc(91.26,79.24) 91.11,79.21 90.99,79.21 arc(90.73,79.16) 90.51,79.01 90.26,78.76 arc(86.29,72.82) 84.89,65.81 84.89,65.4 arc(84.94,65.16) 85.08,64.96 85.11,64.93 arc(85.22,64.76) 85.26,64.55 arc(85.22,64.34) 85.11,64.17 85.03,64.1 arc(84.93,63.94) 84.89,63.76 84.89,63.72 arc(84.92,63.57) 85,63.45 85.11,63.35 arc(85.22,63.18) 85.26,62.98 arc(85.22,62.78) 85.11,62.61 85.08,62.58 arc(84.94,62.37) 84.89,62.13 84.89,61.2 arc(84.94,60.98) v1(85.06,60.8)
  BOTTOM w0.178: U2.4 80.77,55.76 80.8,55.74 81.67,55.74 arc(82.46,55.89) 83.12,56.34 84.28,57.49 arc(84.73,58.18) 84.89,58.98 84.89,60.4 arc(84.94,60.62) v1(85.06,60.8)
N16748096: length 80.9
  TOP w0.178: v1(86.65,56.76) 86.74,56.67 arc(86.83,56.61) 86.93,56.59 87.46,56.59 arc(88.3,56.76) 89.02,57.24 89.74,57.96 arc(90.52,59.12) 90.79,60.49 90.79,69.75 arc(91.56,73.64) 93.77,76.94 94.72,77.88 108.36,91.53 arc(110.41,92.9) 112.83,93.38 130.88,93.38 arc(132.92,92.97) 134.64,91.82 134.79,91.67 135.35,91.11 arc(135.77,90.49) 135.91,89.75 135.91,89.21 C5.2
  BOTTOM w0.178: U2.5 80.8,55.3 82.78,55.3 arc(83.3,55.4) 83.74,55.69 84.02,55.98 arc(84.71,56.43) 85.52,56.59 86.26,56.59 arc(86.47,56.64) v1(86.65,56.76)
N16748102: length 80.9
  TOP w0.178: C6.2 135.35,89.21 135.35,89.75 arc(135.25,90.27) 134.95,90.72 134.25,91.43 arc(132.7,92.46) 130.88,92.82 130.49,92.82 arc(130.24,92.77) 130.02,92.62 129.97,92.57 arc(129.62,92.43) 129.26,92.57 129.17,92.67 arc(129,92.78) 128.8,92.82 128.75,92.82 arc(128.6,92.79) 128.48,92.71 128.37,92.6 arc(127.96,92.43) 127.55,92.6 127.52,92.62 arc(127.3,92.77) 127.05,92.82 112.83,92.82 arc(110.62,92.38) 108.75,91.13 95.11,77.49 94.16,76.54 arc(92.08,73.42) 91.35,69.75 91.35,69.45 arc(91.39,69.23) 91.52,69.03 arc(91.67,68.67) 91.52,68.31 91.5,68.29 arc(91.35,67.93) 91.5,67.57 91.6,67.47 arc(91.69,67.34) 91.72,67.18 91.72,67.16 arc(91.69,67.02) 91.62,66.9 91.51,66.8 arc(91.39,66.62) 91.35,66.41 91.35,60.49 arc(91.03,58.91) 90.14,57.57 89.41,56.84 arc(88.52,56.25) 87.46,56.03 87.02,56.03 arc(86.82,55.99) v1(86.65,55.87)
  BOTTOM w0.178: U2.6 80.8,54.73 81.03,54.73 81.03,54.74 82.78,54.74 arc(83.52,54.88) 84.14,55.3 84.42,55.58 arc(84.92,55.92) 85.52,56.03 86.26,56.03 arc(86.47,55.99) v1(86.65,55.87)
N16748108: length 19.5
  BOTTOM w0.178: C7.2 91.31,65.31 90.94,65.31 arc(90.13,65.15) 89.44,64.69 88.77,64.02 arc(88.14,63.09) 87.92,61.98 87.92,55.71 arc(87.83,55.25) 87.57,54.86 arc(86.95,54.44) 86.22,54.3 80.8,54.3 U2.7
N16748114: length 19.5
  BOTTOM w0.178: C8.2 91.31,64.75 90.94,64.75 arc(90.34,64.63) 89.83,64.29 89.17,63.63 arc(88.66,62.87) 88.48,61.98 88.48,55.71 arc(88.35,55.03) 87.97,54.46 arc(87.16,53.93) 86.22,53.74 80.8,53.74 U2.8
N16748184: length 13.5
  BOTTOM w0.178: U2.11 80.8,52.24 87.52,52.24 arc(88.29,52.39) 88.94,52.83 89.36,53.24 arc(90,54.21) 90.23,55.34 90.23,55.94 arc(90.46,56.52) 91.04,56.75 91.31,56.75 91.34,56.71 C10.2
N16748188: length 13.5
  BOTTOM w0.178: C9.2 91.31,57.31 91.04,57.31 arc(90.07,56.91) 89.67,55.94 89.67,55.34 arc(89.48,54.42) 88.96,53.64 88.54,53.22 arc(88.07,52.91) 87.52,52.8 80.8,52.8 U2.10
N16748192: length 11.4
  BOTTOM w0.178: U2.13 80.77,51.26 80.8,51.24 81.88,51.24 arc(82.03,51.21) 82.16,51.12 arc(82.45,50.92) 82.8,50.85 87.16,50.85 arc(87.9,50.71) 88.53,50.28 89.4,49.41 arc(90.13,48.92) 90.99,48.75 91.31,48.75 C12.2
N16748196: length 11.4
  BOTTOM w0.178: C11.2 91.31,49.31 90.99,49.31 arc(90.35,49.44) 89.8,49.81 88.92,50.68 arc(88.11,51.22) 87.16,51.41 82.8,51.41 arc(82.67,51.44) 82.55,51.52 arc(82.24,51.72) 81.88,51.8 80.8,51.8 U2.12
N16748388: length 16.3
  BOTTOM w0.178: C13.2 91.31,41.31 90.97,41.31 arc(90.58,41.39) 90.24,41.62 88.7,43.15 arc(87.89,44.37) 87.6,45.81 87.6,46.82 arc(87.31,48.27) 86.49,49.49 arc(85.6,50.09) 84.55,50.3 80.8,50.3 80.77,50.27 U2.15
N16748392: length 16.3
  BOTTOM w0.178: U2.16 80.77,49.77 80.8,49.74 84.55,49.74 arc(85.39,49.57) 86.1,49.1 arc(86.8,48.05) 87.04,46.82 87.04,45.81 arc(87.37,44.16) 88.31,42.76 89.84,41.22 arc(90.36,40.87) 90.97,40.75 91.31,40.75 91.34,40.71 C14.2
N16748396: length 75.8
  TOP w0.178: C15.2 127.91,89.21 127.91,89.51 arc(127.82,89.96) 127.57,90.34 127.21,90.7 arc(126.63,91.09) 125.94,91.23 115.92,91.23 arc(113.24,90.7) 110.97,89.18 97.54,75.76 arc(95.66,72.93) 94.99,69.6 94.99,60.45 arc(94.08,55.87) 91.49,51.99 88.72,49.22 arc(87.4,48.34) 85.85,48.03 85.34,48.03 arc(85.13,48.08) v1(84.94,48.2)
  BOTTOM w0.178: U2.17 80.77,49.27 80.8,49.3 81.31,49.3 arc(81.85,49.19) 82.32,48.88 82.63,48.56 arc(83.22,48.17) 83.91,48.03 84.55,48.03 arc(84.76,48.08) v1(84.94,48.2)
N16748400: length 75.7
  TOP w0.178: C16.2 127.35,89.21 127.35,89.51 arc(127.31,89.75) 127.17,89.95 126.81,90.31 arc(126.41,90.58) 125.94,90.67 124.8,90.67 arc(124.56,90.62) 124.36,90.49 124.32,90.45 arc(123.97,90.3) 123.61,90.45 123.55,90.52 arc(123.38,90.63) 123.18,90.67 123.13,90.67 arc(122.98,90.64) 122.85,90.56 122.74,90.44 arc(122.4,90.3) 122.06,90.44 122.02,90.49 arc(121.81,90.62) 121.57,90.67 115.92,90.67 arc(113.45,90.18) 111.36,88.78 97.94,75.36 arc(96.17,72.72) 95.55,69.6 95.55,69.43 arc(95.6,69.2) 95.73,68.99 95.77,68.96 arc(95.92,68.61) 95.77,68.26 95.7,68.19 arc(95.59,68.02) 95.55,67.82 95.55,67.76 arc(95.58,67.62) 95.66,67.5 95.77,67.39 arc(95.92,67.03) 95.77,66.67 95.73,66.64 arc(95.6,66.44) 95.55,66.2 95.55,60.45 arc(94.6,55.66) 91.88,51.6 89.11,48.83 arc(87.62,47.83) 85.85,47.48 85.34,47.48 arc(85.31,47.48) 85.28,47.48 arc(85.13,47.45) 85,47.37 v1(84.94,47.31)
  BOTTOM w0.178: U2.18 80.77,48.76 80.79,48.74 81.31,48.74 arc(81.64,48.67) 81.92,48.48 82.24,48.17 arc(83,47.66) 83.91,47.48 84.55,47.48 arc(84.76,47.43) v1(84.94,47.31)
N16756859: length 19.8
  TOP w0.178: C24.2 127.35,66.82 127.35,58.26 arc(127.75,56.27) 128.88,54.59 129.64,53.82 arc(130.86,53.01) 132.29,52.72 132.57,52.72 arc(133.45,52.55) 134.2,52.05 134.36,51.88 arc(134.46,51.73) 134.5,51.56 134.5,51.23 U1.45
N16756863: length 19.8
  TOP w0.178: C25.2 127.91,66.82 127.91,58.26 arc(128.27,56.48) 129.27,54.98 130.04,54.22 arc(131.07,53.52) 132.29,53.28 132.57,53.28 arc(133.66,53.06) 134.59,52.44 134.76,52.28 arc(134.98,51.95) 135.06,51.56 135.06,51.23 U1.44
N16756883: length 30.1
  TOP w0.178: U1.43 135.5,51.23 135.5,51.84 arc(135.38,52.46) 135.03,52.98 133.17,54.84 arc(132.71,55.15) 132.18,55.25 131.7,55.25 arc(131.48,55.21) v1(131.3,55.09)
  BOTTOM w0.178: C26.2 113.69,40.75 114.12,40.75 arc(115.1,40.95) 115.93,41.5 129,54.57 arc(129.75,55.07) 130.64,55.25 130.9,55.25 arc(131.12,55.21) v1(131.3,55.09)
N16756887: length 30.9
  TOP w0.178: U1.42 136.06,51.23 136.06,51.84 arc(135.89,52.68) 135.42,53.38 134.44,54.36 133.56,55.24 arc(132.93,55.66) 132.18,55.81 131.7,55.81 arc(131.48,55.85) v1(131.3,55.98)
  BOTTOM w0.178: C27.2 113.69,41.31 114.12,41.31 arc(114.89,41.46) 115.53,41.89 128.6,54.97 arc(129.54,55.59) 130.64,55.81 130.9,55.81 arc(131.12,55.85) v1(131.3,55.98)
N16756955: length 36.9
  TOP w0.178: U1.34 140.06,51.23 140.06,56.36 arc(140.1,56.57) v1(140.22,56.76)
  BOTTOM w0.178: C33.2 113.69,65.31 130.98,65.31 arc(134.36,64.64) 137.23,62.72 137.75,62.21 138.64,61.31 138.91,61.05 arc(139.76,59.77) 140.06,58.27 140.06,57.16 arc(140.1,56.94) v1(140.22,56.76)
N16756959: length 36.9
  TOP w0.178: U1.35 139.5,51.23 139.5,56.36 arc(139.46,56.57) v1(139.33,56.76)
  BOTTOM w0.178: C32.2 113.69,64.75 127.13,64.75 arc(127.28,64.72) 127.41,64.64 127.58,64.47 arc(127.76,64.34) 127.98,64.3 128,64.3 arc(128.23,64.34) 128.43,64.48 128.59,64.63 arc(128.88,64.75) 129.17,64.63 129.41,64.4 arc(129.72,64.27) 130.04,64.4 130.19,64.55 arc(130.42,64.7) 130.69,64.75 130.98,64.75 arc(134.15,64.12) 136.83,62.33 137.16,62 arc(137.24,61.88) 137.27,61.74 137.27,61.46 arc(137.29,61.36) 137.35,61.28 137.45,61.17 arc(137.58,61.09) 137.73,61.06 137.91,61.06 arc(138.09,61.02) 138.24,60.92 138.51,60.65 arc(139.24,59.56) 139.5,58.27 139.5,57.16 arc(139.46,56.94) v1(139.33,56.76)
N16756979: length 18.6
  TOP w0.178: C35.2 135.91,66.82 135.91,66.14 arc(136.1,65.21) 136.63,64.41 140.14,60.9 141.72,59.32 arc(142.25,58.52) 142.44,57.57 142.44,56.4 arc(142.33,55.8) 141.99,55.3 141.39,54.7 arc(141.14,54.33) 141.06,53.9 141.06,51.23 U1.32
N16756983: length 18.6
  TOP w0.178: C34.2 135.35,66.82 135.35,66.14 arc(135.58,64.99) 136.23,64.02 139.74,60.51 141.32,58.93 arc(141.74,58.31) 141.88,57.57 141.88,56.4 arc(141.81,56.02) 141.6,55.7 140.99,55.1 arc(140.63,54.55) 140.5,53.9 140.5,51.23 U1.33
N16757079: length 16.5
  TOP w0.178: U1.31 141.5,51.23 141.5,52.31 arc(141.63,52.99) 142.01,53.56 142.49,54.03 arc(143.51,55.57) 143.87,57.37 143.87,63.17 arc(143.82,63.45) 143.66,63.68 arc(143.43,64.05) 143.35,64.47 143.35,66.82 C36.2
N16757083: length 16.5
  TOP w0.178: U1.30 142.06,51.23 142.06,52.31 arc(142.15,52.77) 142.41,53.16 142.88,53.64 arc(144.03,55.35) 144.43,57.37 144.43,63.17 arc(144.34,63.66) 144.06,64.07 arc(143.95,64.26) 143.91,64.47 143.91,66.82 C37.2
N16757087: length 19
  TOP w0.178: C38.2 151.35,66.82 151.35,64 arc(150.8,61.2) 149.21,58.83 144.06,53.68 142.92,52.53 arc(142.61,52.07) 142.5,51.51 142.5,51.23 U1.29
N16757091: length 19
  TOP w0.178: C39.2 151.91,66.82 151.91,64 arc(151.31,60.98) 149.61,58.43 143.32,52.14 arc(143.12,51.85) 143.06,51.51 143.06,51.23 U1.28
N16766495: length 80.8
  TOP w0.203: v1(147.23,50.9) 146.79,51.35 144.77,51.35 143.97,50.55 U1.27
  TOP w0.508: D2.1 v1(201.69,2.43)
  BOTTOM w0.203: v1(147.23,50.9) 147.23,49.26 194.07,2.43 v1(201.69,2.43)
N16781830: length 31.3
  TOP w0.178: U1.40 137,51.23 137,52.1 arc(136.55,54.36) 135.27,56.28 133.75,57.8 arc(133.62,57.88) 133.47,57.91 133.18,57.91 arc(133.07,57.89) 132.97,57.83 v1(132.9,57.75)
  BOTTOM w0.178: C28.2 113.69,48.75 115,48.75 arc(116.97,49.14) 118.63,50.26 125.04,56.67 arc(126.42,57.59) 128.05,57.91 132.61,57.91 arc(132.72,57.89) 132.81,57.83 v1(132.9,57.75)
N16781832: length 32.2
  TOP w0.178: v1(132.9,58.64) 132.97,58.56 arc(133.07,58.5) 133.19,58.47 133.47,58.47 arc(133.84,58.4) 134.14,58.19 135.66,56.67 arc(137.06,54.58) 137.56,52.1 137.56,51.23 U1.39
  BOTTOM w0.178: C29.2 113.69,49.31 115,49.31 arc(116.75,49.66) 118.24,50.65 124.65,57.06 arc(126.21,58.11) 128.05,58.47 132.61,58.47 arc(132.72,58.49) 132.81,58.56 v1(132.9,58.64)
N16781834: length 34.7
  TOP w0.178: U1.38 138,51.23 138,54.66 arc(137.93,55.02) 137.72,55.33 arc(137.28,55.99) 137.13,56.76 137.13,58.05 arc(137.09,58.26) v1(136.96,58.45)
  BOTTOM w0.178: C30.2 113.69,56.75 115.16,56.75 arc(116.14,56.95) 116.98,57.51 117.14,57.67 arc(117.29,57.77) 117.47,57.8 117.73,57.8 arc(117.92,57.84) 118.09,57.95 arc(118.19,58.12) 118.23,58.31 118.23,58.55 arc(118.27,58.74) 118.39,58.91 118.67,59.2 arc(120.66,60.53) 123,60.99 130.41,60.99 arc(130.59,60.96) 130.74,60.85 130.91,60.68 arc(131.24,60.54) 131.57,60.68 131.74,60.84 arc(132.09,60.99) 132.45,60.84 132.6,60.69 arc(132.92,60.56) 133.24,60.69 133.37,60.82 arc(133.55,60.95) 133.77,60.99 134.01,60.99 arc(135.36,60.72) 136.5,59.96 136.93,59.53 arc(137.08,59.31) 137.13,59.05 137.13,58.85 arc(137.09,58.63) v1(136.96,58.45)
N16781836: length 34.7
  TOP w0.178: U1.37 138.56,51.23 138.56,54.66 arc(138.44,55.24) 138.11,55.73 arc(137.8,56.2) 137.69,56.76 137.69,58.05 arc(137.73,58.26) v1(137.85,58.45)
  BOTTOM w0.178: C31.2 113.69,57.31 115.16,57.31 arc(115.93,57.46) 116.58,57.9 118.27,59.59 arc(120.44,61.04) 123,61.55 134.01,61.55 arc(135.57,61.24) 136.9,60.35 137.33,59.92 arc(137.59,59.52) 137.69,59.05 137.69,58.85 arc(137.73,58.63) v1(137.85,58.45)
N143603151: length 3
  TOP w0.203: R8.2 SW1.4
N143603431: length 3
  TOP w0.203: R10.2 SW1.5
N143603671: length 3
  TOP w0.203: R7.2 SW1.3
N143605131: length 3
  TOP w0.203: R3.2 SW1.2
N143605431: length 3
  TOP w0.203: R12.2 SW1.6
N143605671: length 3
  TOP w0.203: R1.2 SW1.1
N144872111: length 3.1
  BOTTOM w0.203: R23.2 SW4.6
N144872810: length 3.1
  BOTTOM w0.203: R13.2 SW4.1
N144872811: length 3.1
  BOTTOM w0.203: R16.2 SW4.2
N144872812: length 3.1
  BOTTOM w0.203: R18.2 SW4.3
N144872813: length 3.1
  BOTTOM w0.203: R19.2 SW4.4
N144872814: length 3.1
  BOTTOM w0.203: R21.2 SW4.5
N144873671: length 3.2
  BOTTOM w0.203: R20.2 210.69,71.01 SW3.4
N144874091: length 3.1
  BOTTOM w0.203: R24.2 SW3.6
N144874331: length 3.1
  BOTTOM w0.203: R22.2 SW3.5
N144874811: length 3.1
  BOTTOM w0.203: R15.2 SW3.3
N144875811: length 3.1
  BOTTOM w0.203: R14.2 SW3.1
N144876491: length 3.1
  BOTTOM w0.203: R17.2 SW3.2
N144883340: length 3
  TOP w0.203: SW8.1 R35.2
N144883341: length 3
  TOP w0.203: SW8.2 R36.2
N144883342: length 3
  TOP w0.203: SW8.3 R37.2
N144883343: length 3
  TOP w0.203: SW8.4 R38.2
N144883344: length 3
  TOP w0.203: SW8.5 R39.2
N144883345: length 3
  TOP w0.203: R40.2 SW8.6
N144883781: length 2.9
  TOP w0.203: SW5.1 R25.2
N144886021: length 2.9
  TOP w0.203: SW5.2 R27.2
N144888661: length 2.9
  TOP w0.203: SW5.6 R33.2
N144889101: length 2.9
  TOP w0.203: SW5.3 R29.2
N144890181: length 2.9
  TOP w0.203: SW5.4 R31.2
N144890984: length 2.9
  TOP w0.203: SW5.5 R32.2
N167546071: length 2.9
  BOTTOM w0.203: R60.2 SW11.6
